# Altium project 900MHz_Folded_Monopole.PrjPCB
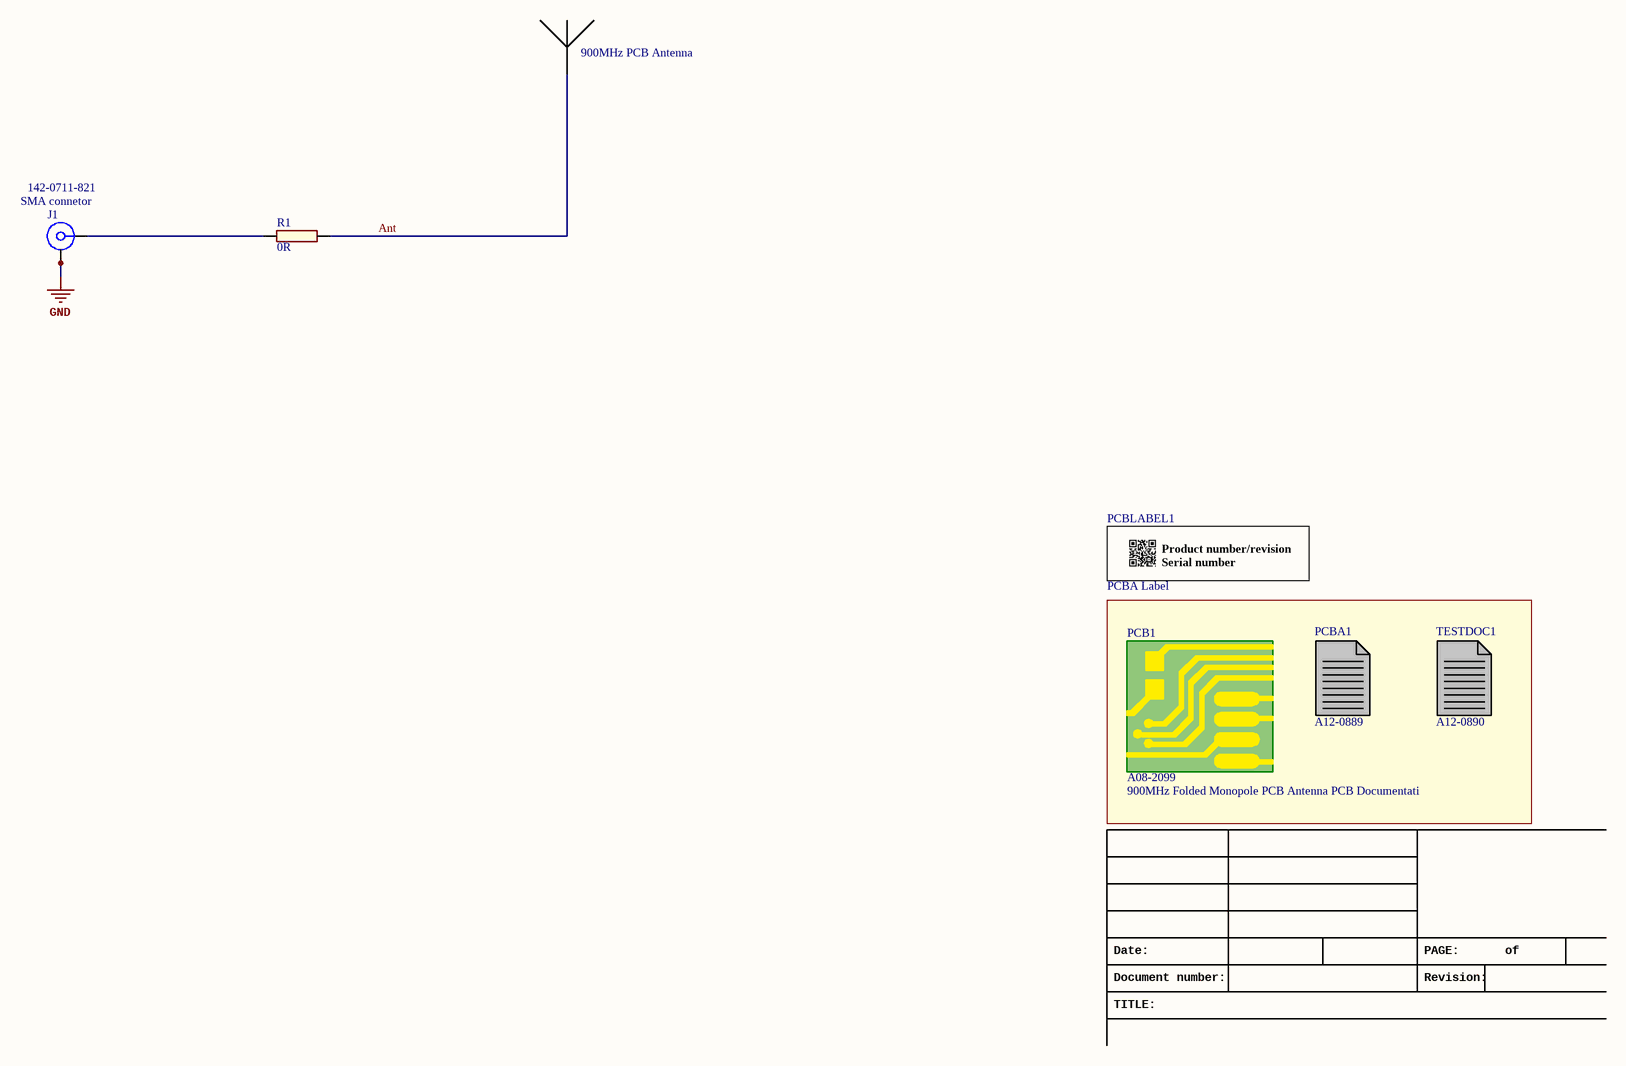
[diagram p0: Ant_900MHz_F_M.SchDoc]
1 sheet, 6 parts. Net scope: global (net labels, ports and power ports of the same name join across sheets).
Board file: Ant_900MHz_F_M.PcbDoc

## Sheet Ant_900MHz_F_M.SchDoc: 900MHz PCB Antenna Schematics
size A3; Organization: ATMEL Norway; Address1: Vestre Rosten 79; Address2: N-7075 TILLER; Address3: NORWAY; DocumentNumber: A09-2311; Revision: 1; SheetNumber: 1; SheetTotal: 1; PageSetup: Record=PageOptions¦CenterHorizontal=True¦CenterVertical=True¦PrintScale=1.01¦XCorrection=1.00¦YCorrection=1.00¦PrintKind=1¦BorderSize=5000000¦LeftOffset=0¦BottomOffset=0¦Orientation=2¦PaperLength=1000¦PaperWidth=1000¦Scale=100¦PaperSource=7¦PrintQuality=-4¦MediaType=1¦DitherType=10¦PaperKind=Letter¦PrintScaleMode=1

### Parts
J1  SMA connetor  value 142-0711-821  [AP8-00443]
PCB1  value 900MHz Folded Monopole PCB Antenna PCB Documentati  AN: A08-2099  (hidden comment: PCB)  (mechanical)
PCBA1  AN: A12-0889  (hidden comment: PCBADOC)  (mechanical)
PCBLABEL1  value PCBA Label  [AP8-00317]  (hidden comment: PCBA_LABEL)
R1  value 0R  [AP2-00000]  (hidden comment: Comment)
TESTDOC1  AN: A12-0890  (hidden comment: TESTDOC)  (mechanical)

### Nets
GND: J1.2 J1.2.1
Ant: R1.2
NetJ1_1: J1.1 R1.1

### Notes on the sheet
- 900MHz PCB Antenna
- Date:
- PAGE:
- of
- TITLE:
- Document number:
- Revision:

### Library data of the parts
J1 = A08-1047: End Launch Jack Receptacle, Round Contact (de21535); Manufacturer: EMERSON; PartGroup: Mechanical devices,Connectors,Coaxial; Art.-Nr.: 21535; ComponentStatus: 'Active (verified)'
PCB1 = A08-2099: 900MHz Folded Monopole PCB Antenna PCB Documentatio; PartGroup: Mechanical devices,Printed circuit boards; TemperatureRange: 0 deg C to +85 deg C; ComponentStatus: 'New (not verified)'
PCBA1 = A12-0889: 900MHz Folded Monopole PCB Antenna PCBA documentation; PartGroup: Documentation,PCBA Documents,Atmel; ComponentStatus: 'New (not verified)'
PCBLABEL1 = A09-0611: PCBA identification label PP Top White Gloss; PartGroup: Mechanical devices,Packaging materials,Printed Labels; Manufacturer: ACT Logimark AS; MPN: 505462; ComponentStatus: 'Active (verified)'
R1 = A02-0163: RES 0.0 OHM 1/16W 0402 SMD; PartGroup: Resistors,SMD,0402 1%; Manufacturer: (n/a); MPN: RMCF0402ZT0R00; Tolerance: 1 %; TemperatureRange: -55 - +125 deg C; ComponentStatus: 'Active (verified)'
TESTDOC1 = A12-0890: 900MHz PCB Antenna Production test instructions; PartGroup: Documentation,Procedures,Test Instructions; ComponentStatus: 'New (not verified)'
